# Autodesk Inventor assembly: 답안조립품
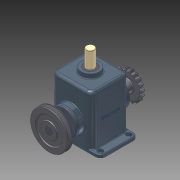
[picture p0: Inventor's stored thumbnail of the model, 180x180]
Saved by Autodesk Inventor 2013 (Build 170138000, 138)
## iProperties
Created: 2015-01
Part Number: 답안조립품
Document SubType Name: Assembly
Designer: Administrator
Mass: 8618.01 g
Surface Area: 4424.06 cm^2
Volume: 1987.46 cm^3
Density: 4.33619 g/cm^3
Author: Administrator
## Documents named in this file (15)
- C:\Users\Administrator\Desktop\350106V1034\답안조립품.iam
- C:\Users\Administrator\Desktop\350106V1034\M4x0.5.ipt
- C:\Users\Administrator\Desktop\350106V1034\V-벨트풀리.ipt
- C:\Users\Administrator\Desktop\350106V1034\가변스프링.ipt
- C:\Users\Administrator\Desktop\350106V1034\멈춤나사 M5x0.5.ipt
- C:\Users\Administrator\Desktop\350106V1034\멈춤링.ipt
- C:\Users\Administrator\Desktop\350106V1034\베어링 6205.ipt
- C:\Users\Administrator\Desktop\350106V1034\본체.ipt
- C:\Users\Administrator\Desktop\350106V1034\부시.ipt
- C:\Users\Administrator\Desktop\350106V1034\슬라이드.ipt
- C:\Users\Administrator\Desktop\350106V1034\오일실.ipt
- C:\Users\Administrator\Desktop\350106V1034\체인 스프로킷.ipt
- C:\Users\Administrator\Desktop\350106V1034\커버.ipt
- C:\Users\Administrator\Desktop\350106V1034\키 8x8.ipt
- C:\Users\Administrator\Desktop\350106V1034\편심축.ipt
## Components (9 placed, 4 different names)
1. V-벨트풀리:1 — 각도:1
2. 가변스프링:1
3. 5-체인 스프로킷:1
4. M4x0.5:1
5. M4x0.5:3
6. M4x0.5:4
7. M4x0.5:2
8. M4x0.5:5
9. M4x0.5:6
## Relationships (1: Angle 1)
- 각도:1 [Angle]: V-벨트풀리:1
